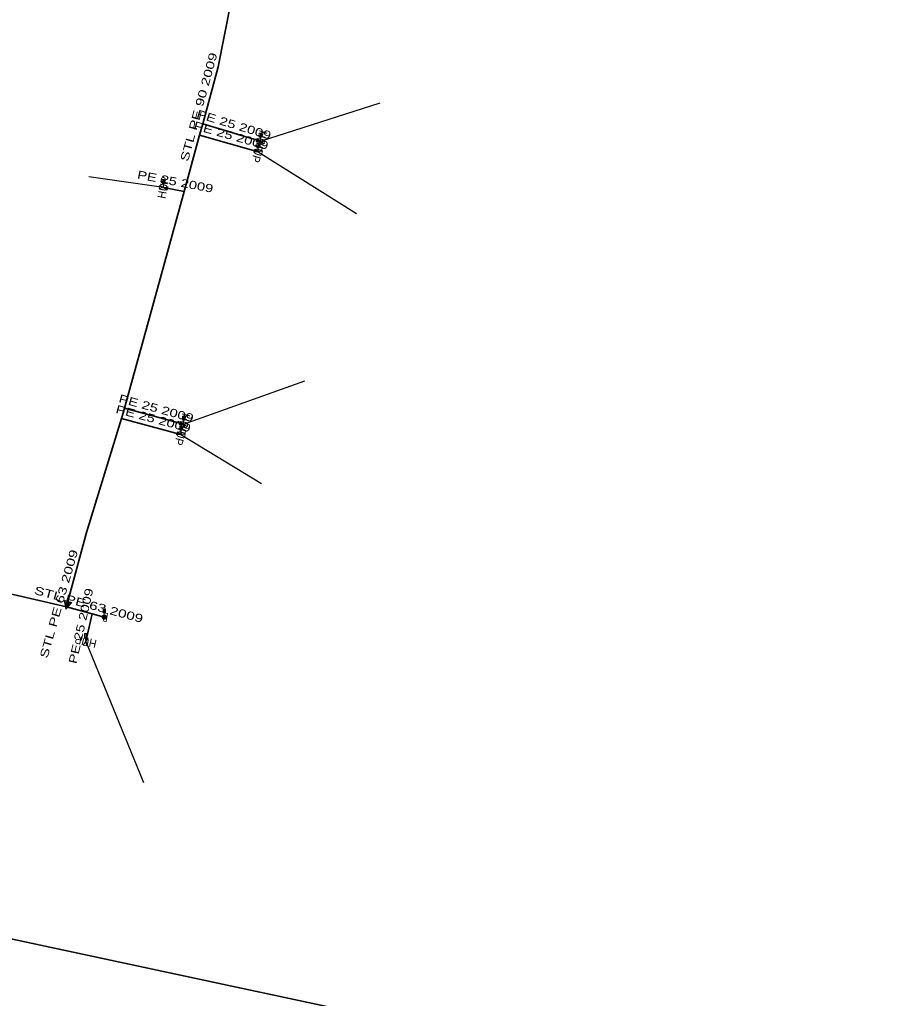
# Model space of a CAD drawing. Extents: x -737484 to -734496, y -1033882 to -1030666.
# Drawn here: x -735727.6 to -735619.4, y -1033042.2 to -1032922.2 of the extents above; entities that cross this region are included whole.
import ezdxf
from ezdxf.enums import TextEntityAlignment as Align

# ---------------------------------------------------------------- set-up
doc = ezdxf.new("R2010")
doc.units = 0
doc.header["$LTSCALE"] = 0.4
for name, color, linetype, lineweight in [('1', 7, 'Continuous', 13), ('22', 7, 'Continuous', 25), ('5', 7, 'Continuous', 35), ('7', 7, 'Continuous', 35)]:
    doc.layers.add(name, color=color, linetype=linetype, lineweight=lineweight)
doc.layers.add('2', color=7, linetype='Continuous')

msp = doc.modelspace()

# ---------------------------------------------------------------- linework, layer by layer
at = {"layer": '1'}
for p, q in [((-735698.143, -1032937.132), (-735698.143, -1032936.632)), ((-735698.068, -1032936.557), (-735698.068, -1032936.207)), ((-735698.427, -1032938.419), (-735698.427, -1032937.919)), ((-735698.352, -1032937.844), (-735698.352, -1032937.494)), ((-735709.957, -1032942.245), (-735709.957, -1032941.895)), ((-735710.032, -1032942.82), (-735710.032, -1032942.32)), ((-735707.483, -1032971.234), (-735707.483, -1032970.884)), ((-735707.558, -1032971.809), (-735707.558, -1032971.309)), ((-735707.881, -1032973.059), (-735707.881, -1032972.559)), ((-735707.806, -1032972.484), (-735707.806, -1032972.134)), ((-735717.202, -1032994.869), (-735717.202, -1032994.519)), ((-735717.389, -1032995.931), (-735717.277, -1032995.444)), ((-735717.277, -1032995.444), (-735717.277, -1032994.944)), ((-735719.544, -1032998.455), (-735719.544, -1032997.955)), ((-735719.469, -1032997.88), (-735719.469, -1032997.53))]:
    msp.add_line(p, q, dxfattribs=at)
for points in [[(-735697.606, -1032937.086), (-735697.723, -1032937.469), (-735698.562, -1032936.794), (-735698.679, -1032937.177)], [(-735698.143, -1032936.132), (-735698.293, -1032936.132), (-735698.293, -1032936.632), (-735698.143, -1032936.632)], [(-735698.143, -1032936.132), (-735697.993, -1032936.132), (-735697.993, -1032936.632), (-735698.143, -1032936.632)], [(-735698.106, -1032936.17), (-735698.031, -1032936.17), (-735698.031, -1032936.595), (-735698.106, -1032936.595)], [(-735697.891, -1032938.364), (-735698.001, -1032938.749), (-735698.852, -1032938.088), (-735698.962, -1032938.473)], [(-735698.427, -1032937.419), (-735698.577, -1032937.419), (-735698.577, -1032937.919), (-735698.427, -1032937.919)], [(-735698.427, -1032937.419), (-735698.277, -1032937.419), (-735698.277, -1032937.919), (-735698.427, -1032937.919)], [(-735698.39, -1032937.457), (-735698.315, -1032937.457), (-735698.315, -1032937.882), (-735698.39, -1032937.882)], [(-735710.032, -1032941.82), (-735710.182, -1032941.82), (-735710.182, -1032942.32), (-735710.032, -1032942.32)], [(-735710.032, -1032941.82), (-735709.882, -1032941.82), (-735709.882, -1032942.32), (-735710.032, -1032942.32)], [(-735709.995, -1032941.858), (-735709.92, -1032941.858), (-735709.92, -1032942.283), (-735709.995, -1032942.283)], [(-735710.56, -1032942.92), (-735710.484, -1032942.528), (-735709.579, -1032943.111), (-735709.503, -1032942.719)], [(-735707.558, -1032970.809), (-735707.708, -1032970.809), (-735707.708, -1032971.309), (-735707.558, -1032971.309)], [(-735707.558, -1032970.809), (-735707.408, -1032970.809), (-735707.408, -1032971.309), (-735707.558, -1032971.309)], [(-735707.521, -1032970.847), (-735707.446, -1032970.847), (-735707.446, -1032971.272), (-735707.521, -1032971.272)], [(-735707.023, -1032971.745), (-735707.126, -1032972.131), (-735707.989, -1032971.486), (-735708.092, -1032971.872)], [(-735707.881, -1032972.059), (-735708.031, -1032972.059), (-735708.031, -1032972.559), (-735707.881, -1032972.559)], [(-735707.881, -1032972.059), (-735707.731, -1032972.059), (-735707.731, -1032972.559), (-735707.881, -1032972.559)], [(-735707.844, -1032972.097), (-735707.769, -1032972.097), (-735707.769, -1032972.522), (-735707.844, -1032972.522)], [(-735707.346, -1032972.995), (-735707.449, -1032973.381), (-735708.312, -1032972.736), (-735708.415, -1032973.122)], [(-735721.234, -1032993.646), (-735722.2, -1032993.387), (-735721.976, -1032994.482)], [(-735722.069, -1032993.526), (-735721.918, -1032994.266), (-735721.416, -1032993.701)], [(-735721.86, -1032994.051), (-735721.599, -1032993.755), (-735721.94, -1032993.664)], [(-735717.277, -1032994.444), (-735717.427, -1032994.444), (-735717.427, -1032994.944), (-735717.277, -1032994.944)], [(-735717.277, -1032994.444), (-735717.127, -1032994.444), (-735717.127, -1032994.944), (-735717.277, -1032994.944)], [(-735717.24, -1032994.482), (-735717.165, -1032994.482), (-735717.165, -1032994.907), (-735717.24, -1032994.907)], [(-735717.321, -1032995.69), (-735717.344, -1032995.684), (-735717.368, -1032995.676), (-735717.391, -1032995.667), (-735717.411, -1032995.654), (-735717.432, -1032995.64), (-735717.45, -1032995.624), (-735717.467, -1032995.606), (-735717.482, -1032995.586), (-735717.495, -1032995.566), (-735717.506, -1032995.543), (-735717.514, -1032995.521), (-735717.521, -1032995.497), (-735717.524, -1032995.472), (-735717.527, -1032995.448), (-735717.525, -1032995.424), (-735717.523, -1032995.399), (-735717.517, -1032995.375), (-735717.509, -1032995.352), (-735717.5, -1032995.329), (-735717.486, -1032995.308), (-735717.473, -1032995.288), (-735717.456, -1032995.27), (-735717.439, -1032995.253), (-735717.419, -1032995.238), (-735717.398, -1032995.224), (-735717.376, -1032995.214), (-735717.353, -1032995.205), (-735717.33, -1032995.199), (-735717.305, -1032995.195), (-735717.281, -1032995.193), (-735717.257, -1032995.194), (-735717.232, -1032995.197), (-735717.209, -1032995.203), (-735717.185, -1032995.21), (-735717.162, -1032995.22), (-735717.142, -1032995.232), (-735717.121, -1032995.247), (-735717.102, -1032995.263), (-735717.086, -1032995.281), (-735717.071, -1032995.3), (-735717.057, -1032995.322), (-735717.047, -1032995.344), (-735717.038, -1032995.366), (-735717.032, -1032995.39), (-735717.027, -1032995.414), (-735717.026, -1032995.439), (-735717.027, -1032995.463), (-735717.03, -1032995.487), (-735717.036, -1032995.511), (-735717.043, -1032995.535), (-735717.053, -1032995.558), (-735717.065, -1032995.578), (-735717.08, -1032995.599), (-735717.096, -1032995.618), (-735717.114, -1032995.634), (-735717.133, -1032995.649), (-735717.154, -1032995.662), (-735717.177, -1032995.673), (-735717.199, -1032995.682), (-735717.223, -1032995.688), (-735717.248, -1032995.691), (-735717.272, -1032995.694), (-735717.296, -1032995.692)], [(-735717.104, -1032995.474), (-735717.108, -1032995.491), (-735717.113, -1032995.507), (-735717.12, -1032995.523), (-735717.129, -1032995.538), (-735717.138, -1032995.552), (-735717.151, -1032995.565), (-735717.163, -1032995.577), (-735717.176, -1032995.587), (-735717.191, -1032995.597), (-735717.206, -1032995.605), (-735717.223, -1032995.61), (-735717.239, -1032995.614), (-735717.256, -1032995.618), (-735717.273, -1032995.619), (-735717.29, -1032995.618), (-735717.307, -1032995.616), (-735717.324, -1032995.612), (-735717.341, -1032995.606), (-735717.356, -1032995.6), (-735717.371, -1032995.591), (-735717.385, -1032995.581), (-735717.398, -1032995.569), (-735717.41, -1032995.557), (-735717.42, -1032995.544), (-735717.429, -1032995.528), (-735717.437, -1032995.513), (-735717.443, -1032995.497), (-735717.447, -1032995.481), (-735717.451, -1032995.464), (-735717.452, -1032995.446), (-735717.451, -1032995.429), (-735717.449, -1032995.412), (-735717.445, -1032995.395), (-735717.439, -1032995.379), (-735717.432, -1032995.363), (-735717.424, -1032995.349), (-735717.414, -1032995.335), (-735717.402, -1032995.322), (-735717.39, -1032995.309), (-735717.377, -1032995.299), (-735717.361, -1032995.291), (-735717.346, -1032995.283), (-735717.33, -1032995.276), (-735717.314, -1032995.272), (-735717.297, -1032995.269), (-735717.279, -1032995.268), (-735717.263, -1032995.269), (-735717.245, -1032995.271), (-735717.228, -1032995.275), (-735717.212, -1032995.281), (-735717.196, -1032995.288), (-735717.182, -1032995.296), (-735717.168, -1032995.305), (-735717.155, -1032995.317), (-735717.142, -1032995.33), (-735717.132, -1032995.343), (-735717.123, -1032995.358), (-735717.115, -1032995.373), (-735717.11, -1032995.39), (-735717.105, -1032995.406), (-735717.102, -1032995.423), (-735717.101, -1032995.44), (-735717.101, -1032995.457)], [(-735717.424, -1032995.417), (-735717.421, -1032995.402), (-735717.416, -1032995.389), (-735717.41, -1032995.375), (-735717.402, -1032995.362), (-735717.395, -1032995.351), (-735717.385, -1032995.339), (-735717.373, -1032995.329), (-735717.362, -1032995.32), (-735717.35, -1032995.313), (-735717.336, -1032995.306), (-735717.323, -1032995.3), (-735717.308, -1032995.297), (-735717.293, -1032995.294), (-735717.279, -1032995.293), (-735717.264, -1032995.293), (-735717.25, -1032995.296), (-735717.235, -1032995.299), (-735717.222, -1032995.303), (-735717.208, -1032995.31), (-735717.195, -1032995.317), (-735717.184, -1032995.325), (-735717.172, -1032995.335), (-735717.162, -1032995.346), (-735717.153, -1032995.358), (-735717.145, -1032995.37), (-735717.138, -1032995.383), (-735717.133, -1032995.397), (-735717.13, -1032995.412), (-735717.127, -1032995.426), (-735717.126, -1032995.44), (-735717.126, -1032995.456), (-735717.129, -1032995.469), (-735717.132, -1032995.484), (-735717.136, -1032995.498), (-735717.142, -1032995.511), (-735717.149, -1032995.524), (-735717.158, -1032995.536), (-735717.168, -1032995.548), (-735717.179, -1032995.557), (-735717.19, -1032995.567), (-735717.203, -1032995.574), (-735717.216, -1032995.581), (-735717.23, -1032995.587), (-735717.245, -1032995.59), (-735717.259, -1032995.592), (-735717.273, -1032995.593), (-735717.288, -1032995.593), (-735717.302, -1032995.591), (-735717.317, -1032995.588), (-735717.331, -1032995.583), (-735717.344, -1032995.577), (-735717.357, -1032995.57), (-735717.369, -1032995.562), (-735717.381, -1032995.552), (-735717.39, -1032995.54), (-735717.4, -1032995.529), (-735717.407, -1032995.517), (-735717.413, -1032995.503), (-735717.42, -1032995.49), (-735717.423, -1032995.475), (-735717.425, -1032995.461), (-735717.427, -1032995.446), (-735717.426, -1032995.432)], [(-735717.35, -1032995.43), (-735717.349, -1032995.423), (-735717.346, -1032995.416), (-735717.344, -1032995.41), (-735717.339, -1032995.403), (-735717.336, -1032995.397), (-735717.33, -1032995.391), (-735717.325, -1032995.386), (-735717.319, -1032995.381), (-735717.313, -1032995.378), (-735717.307, -1032995.374), (-735717.299, -1032995.372), (-735717.292, -1032995.37), (-735717.285, -1032995.369), (-735717.278, -1032995.368), (-735717.27, -1032995.368), (-735717.264, -1032995.37), (-735717.256, -1032995.371), (-735717.249, -1032995.373), (-735717.243, -1032995.376), (-735717.235, -1032995.38), (-735717.23, -1032995.384), (-735717.224, -1032995.389), (-735717.219, -1032995.394), (-735717.214, -1032995.4), (-735717.21, -1032995.406), (-735717.208, -1032995.413), (-735717.204, -1032995.42), (-735717.203, -1032995.428), (-735717.202, -1032995.435), (-735717.201, -1032995.442), (-735717.202, -1032995.449), (-735717.203, -1032995.456), (-735717.204, -1032995.463), (-735717.207, -1032995.471), (-735717.209, -1032995.477), (-735717.213, -1032995.484), (-735717.217, -1032995.49), (-735717.222, -1032995.495), (-735717.228, -1032995.501), (-735717.233, -1032995.505), (-735717.239, -1032995.509), (-735717.246, -1032995.512), (-735717.253, -1032995.515), (-735717.261, -1032995.517), (-735717.267, -1032995.519), (-735717.275, -1032995.519), (-735717.282, -1032995.518), (-735717.289, -1032995.517), (-735717.297, -1032995.516), (-735717.304, -1032995.513), (-735717.31, -1032995.511), (-735717.317, -1032995.507), (-735717.323, -1032995.503), (-735717.328, -1032995.497), (-735717.334, -1032995.492), (-735717.338, -1032995.486), (-735717.341, -1032995.48), (-735717.345, -1032995.474), (-735717.347, -1032995.466), (-735717.35, -1032995.459), (-735717.35, -1032995.452), (-735717.352, -1032995.445), (-735717.351, -1032995.438)], [(-735719.461, -1032998.987), (-735719.851, -1032998.897), (-735719.236, -1032998.012), (-735719.626, -1032997.922)], [(-735719.544, -1032997.455), (-735719.694, -1032997.455), (-735719.694, -1032997.955), (-735719.544, -1032997.955)], [(-735719.544, -1032997.455), (-735719.394, -1032997.455), (-735719.394, -1032997.955), (-735719.544, -1032997.955)], [(-735719.507, -1032997.493), (-735719.432, -1032997.493), (-735719.432, -1032997.918), (-735719.507, -1032997.918)]]:
    msp.add_lwpolyline(points, close=True, dxfattribs=at)
msp.add_lwpolyline([(-735717.109, -1032994.966), (-735716.863, -1032995.014), (-735717.054, -1032995.995), (-735717.299, -1032995.948)], dxfattribs=at)
at = {"layer": '22'}
for p, q in [((-735698.143, -1032937.132), (-735683.495, -1032932.419)), ((-735698.427, -1032938.419), (-735686.401, -1032945.977)), ((-735710.032, -1032942.82), (-735719.184, -1032941.504)), ((-735707.558, -1032971.809), (-735692.695, -1032966.475)), ((-735707.881, -1032973.059), (-735698.022, -1032979.065)), ((-735719.544, -1032998.455), (-735712.452, -1033015.709))]:
    msp.add_line(p, q, dxfattribs=at)
at = {"layer": '5'}
msp.add_line((-735721.847, -1032994), (-735721.904, -1032994.2), dxfattribs=at)
for points in [[(-735692.941, -1032871.15), (-735696.018, -1032888.289), (-735698.227, -1032900.552), (-735698.462, -1032901.852), (-735701.566, -1032919.085), (-735701.804, -1032920.387), (-735703.319, -1032928.021), (-735705.218, -1032934.981), (-735705.601, -1032936.384), (-735707.49, -1032943.304), (-735711.34, -1032957.273), (-735714.785, -1032969.828), (-735714.962, -1032970.474), (-735715.163, -1032971.128), (-735719.459, -1032985.101), (-735721.847, -1032994)], [(-735453.458, -1033127.579), (-735474.026, -1033120.036), (-735568.61, -1033085.622), (-735678.017, -1033045.757), (-735757.343, -1033028.731), (-735835.562, -1033011.943), (-735873.636, -1033018.428), (-736013.383, -1032980.019), (-736048.427, -1033030.916), (-736049.074, -1033031.856)], [(-735721.904, -1032994.2), (-735730.774, -1032992.163), (-735744.26, -1032989.363), (-735745.598, -1032989.083), (-735751.82, -1032987.835), (-735753.574, -1032987.49), (-735768.253, -1032984.192), (-735783.888, -1032980.577)], [(-735721.904, -1032994.2), (-735718.77, -1032995.043), (-735717.277, -1032995.444), (-735716.959, -1032995.505)]]:
    msp.add_lwpolyline(points, dxfattribs=at)
at = {"layer": '7'}
for p, q in [((-735705.218, -1032934.981), (-735698.143, -1032937.132)), ((-735705.601, -1032936.384), (-735698.427, -1032938.419)), ((-735707.49, -1032943.304), (-735710.032, -1032942.82)), ((-735714.785, -1032969.828), (-735707.558, -1032971.809)), ((-735715.163, -1032971.128), (-735707.881, -1032973.059)), ((-735718.77, -1032995.043), (-735719.544, -1032998.455))]:
    msp.add_line(p, q, dxfattribs=at)

# ---------------------------------------------------------------- texts
at = {"layer": '2', "width": 0.95}
for rotation, p in [(253, (-735698.6208, -1032936.9853)), (254, (-735698.9068, -1032938.2807)), (79, (-735709.5409, -1032942.9149)), (255, (-735708.0403, -1032971.6791)), (255, (-735708.3633, -1032972.9291)), (167, (-735719.431, -1032997.9675))]:
    msp.add_text('HUP', height=1, rotation=rotation, dxfattribs=at).set_placement(p, align=Align.CENTER)
at = {"layer": '5', "width": 1.4}
for s, rotation, p in [('STL PE 90 2009', 74.739, (-735705.2125, -1032933.0631)), ('STL PE 63 2009', 74.092, (-735722.3558, -1032993.9625)), ('STL PE 63 2009', 344.945, (-735719.3039, -1032994.3809))]:
    msp.add_text(s, height=1, rotation=rotation, dxfattribs=at).set_placement(p, align=Align.CENTER)
at = {"layer": '7', "width": 1.35}
for rotation, p in [(343.089, (-735701.5344, -1032935.578)), (344.163, (-735701.8769, -1032936.9197)), (349.22, (-735708.667, -1032942.5705)), (344.671, (-735711.0387, -1032970.3357)), (345.148, (-735711.3932, -1032971.6101)), (77.219, (-735719.6444, -1032996.6381))]:
    msp.add_text('PE 25 2009', height=1, rotation=rotation, dxfattribs=at).set_placement(p, align=Align.CENTER)

doc.saveas('drawing.dxf')
